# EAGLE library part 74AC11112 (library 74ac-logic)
Dual J-K negative edge triggered FLIP FLOP
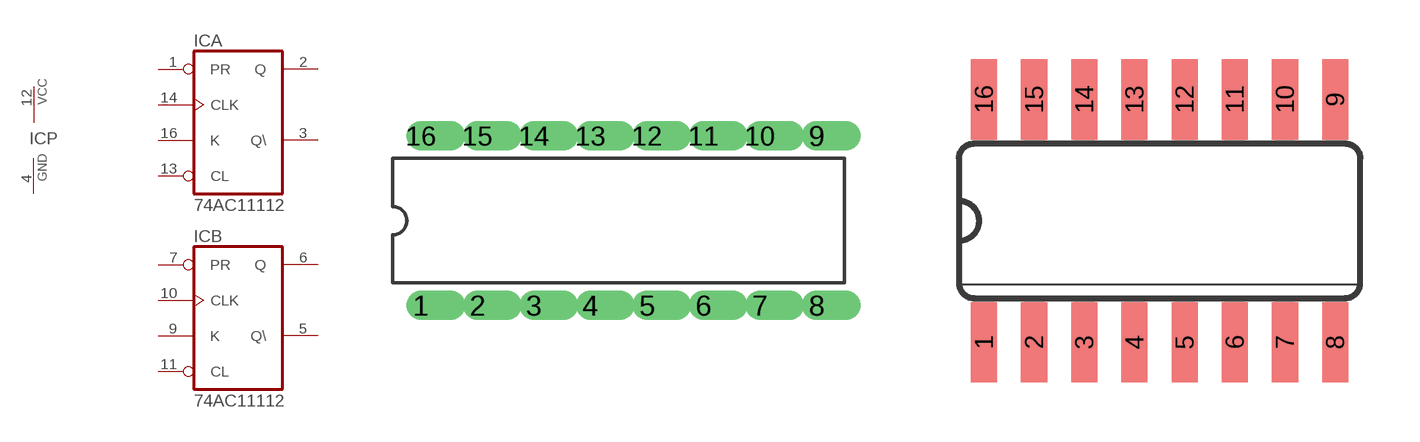
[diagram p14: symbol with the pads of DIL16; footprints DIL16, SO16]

Designator prefix IC; gates A=7411112 B=7411112 P=PWRN

## 74AC11112  [DIL16]
1  A:PR  in
2  A:Q  out
3  A:Q\  out
4  P:GND  pwr
5  B:Q\  out
6  B:Q  out
7  B:PR  in
9  B:K  in
10  B:CLK  in
11  B:CL  in
12  P:VCC  pwr
13  A:CL  in
14  A:CLK  in
16  A:K  in

## 74AC11112D  [SO16]
Pads as for DIL16

## Footprint DIL16 (pad centres in mm)
Dual In Line
drill 0.813 offset: 1 -8.89,-3.81; 2 -6.35,-3.81; 3 -3.81,-3.81; 4 -1.27,-3.81; 5 1.27,-3.81; 6 3.81,-3.81; 7 6.35,-3.81; 8 8.89,-3.81; 9 8.89,3.81; 10 6.35,3.81; 11 3.81,3.81; 12 1.27,3.81; 13 -1.27,3.81; 14 -3.81,3.81; 15 -6.35,3.81; 16 -8.89,3.81

## Footprint SO16 (pad centres in mm)
Small Outline package 150 mil
smd 0.66 x 2.032: 1 -4.445,-3.073; 2 -3.175,-3.073; 3 -1.905,-3.073; 4 -0.635,-3.073; 5 0.635,-3.073; 6 1.905,-3.073; 7 3.175,-3.073; 8 4.445,-3.073; 9 4.445,3.073; 10 3.175,3.073; 11 1.905,3.073; 12 0.635,3.073; 13 -0.635,3.073; 14 -1.905,3.073; 15 -3.175,3.073; 16 -4.445,3.073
